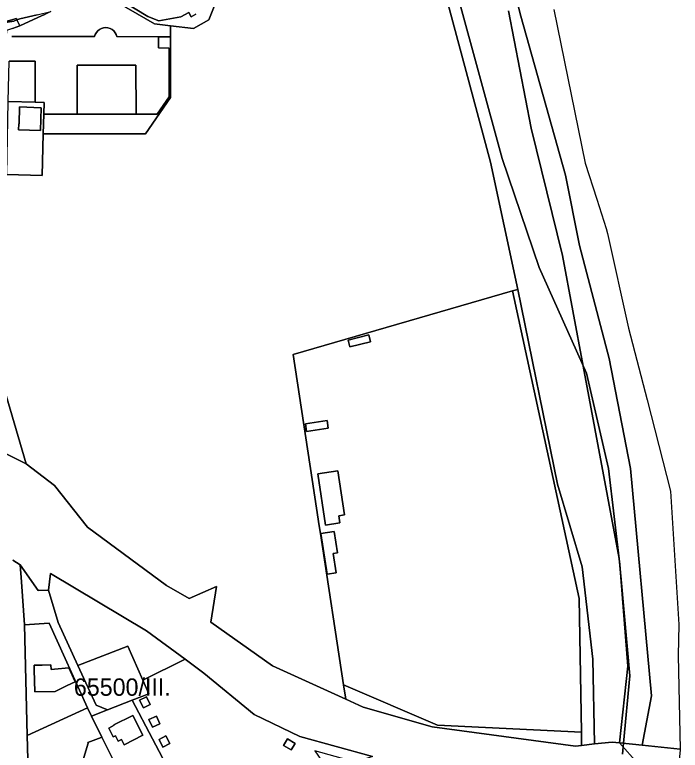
# Model space of a CAD drawing. Extents: x -502026 to -497664, y -1143484 to -1138019.
# Drawn here: x -497970.3 to -497663.8, y -1140661.2 to -1140322.7 of the extents above; entities that cross this region are included whole.
import ezdxf

# ---------------------------------------------------------------- set-up
doc = ezdxf.new("R2010")
doc.units = 0
for name, color, linetype in [('25', 7, 'Continuous'), ('49', 7, 'Continuous'), ('55', 7, 'Continuous'), ('62', 7, 'Continuous'), ('7', 7, 'Continuous')]:
    doc.layers.add(name, color=color, linetype=linetype)

msp = doc.modelspace()

# ---------------------------------------------------------------- linework, layer by layer
at = {"layer": '25'}
for points in [[(-497936.82, -1140641.63), (-497964.62, -1140654.4), (-497965.83, -1140603.55), (-497954.43, -1140602.68)], [(-497805.55, -1140664.16), (-497813.42, -1140666.63), (-497832.11, -1140661.41), (-497812.62, -1140689.68), (-497805.57, -1140699.94), (-497798.59, -1140710.5), (-497772.17, -1140748.77), (-497794.67, -1140765.2), (-497816.79, -1140777.36), (-497824.82, -1140780.89), (-497825.15, -1140780.18), (-497841.74, -1140744.45), (-497858.43, -1140708.44), (-497861.67, -1140701.6), (-497877.43, -1140665.94), (-497897.52, -1140673.81), (-497916.16, -1140638.1), (-497908.61, -1140635.26), (-497911.38, -1140628.95), (-497891.85, -1140619.36), (-497883.28, -1140625.68), (-497860.05, -1140644.73), (-497839.03, -1140654.82)], [(-497953.61, -1140621.9), (-497957.75, -1140621.99), (-497961.43, -1140622.09), (-497961.3, -1140624.22), (-497961.03, -1140634.35), (-497951.67, -1140634.13), (-497946.11, -1140631.47), (-497942.55, -1140629.76), (-497945.46, -1140623.23), (-497951.94, -1140623.97), (-497953.55, -1140624.01)], [(-497907.9, -1140640.14), (-497909.7, -1140636.6), (-497912.83, -1140638.13), (-497911.04, -1140641.71)], [(-497897.52, -1140673.81), (-497917.07, -1140681.47), (-497919.36, -1140677), (-497930.13, -1140655.18), (-497934.91, -1140645.49), (-497927.56, -1140642.59), (-497916.16, -1140638.1)], [(-497934.91, -1140645.49), (-497930.13, -1140655.18), (-497930.45, -1140655.3), (-497936.6, -1140657.61), (-497936.45, -1140658.02), (-497940.31, -1140670.66), (-497939.64, -1140672.96), (-497941.84, -1140673.79), (-497940.2, -1140678.14), (-497938, -1140677.31), (-497937.04, -1140679.84), (-497935.87, -1140682.92), (-497941.97, -1140685.1), (-497953.46, -1140689.2), (-497963.48, -1140692.74), (-497964.62, -1140654.4), (-497936.82, -1140641.63)], [(-497911.25, -1140654.34), (-497915.95, -1140645.14), (-497924.61, -1140649.56), (-497924.51, -1140649.74), (-497927.05, -1140651.04), (-497925.01, -1140655.03), (-497923.97, -1140654.5), (-497922.7, -1140656.99), (-497921.2, -1140656.22), (-497919.95, -1140658.67)], [(-497903.46, -1140649.05), (-497905.1, -1140645.45), (-497908.54, -1140646.99), (-497906.81, -1140650.6)], [(-497898.92, -1140658.15), (-497900.7, -1140654.59), (-497903.83, -1140656.2), (-497902.05, -1140659.73)], [(-497841.21, -1140658.03), (-497844.68, -1140655.93), (-497846.51, -1140658.98), (-497843.04, -1140661.04)]]:
    msp.add_lwpolyline(points, close=True, dxfattribs=at)
at = {"layer": '49'}
msp.add_lwpolyline([(-497722.04, -1140320.29), (-497707.7, -1140391.05), (-497702.32, -1140407.61), (-497697.93, -1140421.1), (-497697.4, -1140423.44), (-497687.61, -1140466.9), (-497679.11, -1140500), (-497668.31, -1140542.04), (-497664.47, -1140603.39), (-497664.79, -1140617.64), (-497663.84, -1140660.72), (-497681.38, -1140658.88), (-497677.05, -1140636.15), (-497686.75, -1140531.6), (-497696.64, -1140480.95), (-497710.3, -1140428.93), (-497716.71, -1140396.51), (-497737.24, -1140323.39), (-497754.99, -1140253.14)], dxfattribs=at)
msp.add_lwpolyline([(-497681.38, -1140658.88), (-497663.84, -1140660.72), (-497663.83, -1140661.21), (-497664.59, -1140668.32), (-497664.63, -1140668.75), (-497665.07, -1140672.88), (-497665.12, -1140673.27), (-497666.55, -1140686.68), (-497686.23, -1140684.57), (-497699.12, -1140683.04), (-497683.84, -1140672.19), (-497683.37, -1140667.28), (-497691.84, -1140657.78)], close=True, dxfattribs=at)
at = {"layer": '55'}
for points in [[(-497691.84, -1140657.78), (-497695.17, -1140657.43), (-497703.28, -1140658.33), (-497704.11, -1140619.29), (-497708.97, -1140576.79), (-497720.33, -1140538.79), (-497738.59, -1140449.11), (-497751.17, -1140390.61), (-497791.01, -1140242.45), (-497784.27, -1140241.09), (-497766.22, -1140314.06), (-497745.87, -1140388.9), (-497728.83, -1140438.98), (-497707.05, -1140487.75), (-497696.93, -1140531.58), (-497691.64, -1140575.72), (-497688.04, -1140622.46)], [(-497956.48, -1140322.59), (-497957.69, -1140323.15), (-497967.99, -1140327.91), (-497969.28, -1140325.11), (-497967.92, -1140324.62), (-497960.03, -1140322.72), (-497953.65, -1140321.27)], [(-497967.99, -1140327.91), (-497971.3, -1140329.05), (-497974.13, -1140330.03), (-497979.11, -1140332.27), (-497981.94, -1140332.89), (-497988.1, -1140334.24), (-497997.64, -1140334.52), (-498008.74, -1140334.09), (-498008.64, -1140332.24), (-498003.4, -1140332.22), (-497996.47, -1140330.02), (-497994.85, -1140329.91), (-497988.93, -1140329.3), (-497983.89, -1140328.52), (-497977.71, -1140326.79), (-497970.78, -1140325.66), (-497969.28, -1140325.11)], [(-497969.28, -1140325.11), (-497970.78, -1140325.66), (-497977.71, -1140326.79), (-497969.56, -1140324.51)], [(-497974.21, -1140332.78), (-497974.36, -1140337.77), (-497974.54, -1140344.08), (-497978.1, -1140485.38), (-497965, -1140529.36), (-497976.1, -1140523.81), (-497986.26, -1140484.05), (-497986.07, -1140460.79), (-497984.83, -1140425.08), (-497983.81, -1140385.99), (-497982.32, -1140365.37), (-497981.91, -1140339.55), (-497981.94, -1140332.89), (-497979.11, -1140332.27), (-497974.13, -1140330.03)], [(-497914.35, -1140368.48), (-497941.57, -1140368.44), (-497941.52, -1140345.9), (-497914.49, -1140345.89)], [(-497958.18, -1140365.56), (-497958.37, -1140375.97), (-497968.51, -1140375.66), (-497968.45, -1140372.95), (-497968.28, -1140372.94), (-497968.08, -1140365.19)], [(-497709.37, -1140652.85), (-497775.61, -1140649.69), (-497818.9, -1140631.1), (-497829.51, -1140561.5), (-497830.05, -1140557.94), (-497833.28, -1140536.67), (-497842.03, -1140479.04), (-497741.17, -1140449.86), (-497710.44, -1140591.41)], [(-497703.28, -1140658.33), (-497709.26, -1140658.99), (-497709.37, -1140652.85), (-497710.44, -1140591.41), (-497741.17, -1140449.86), (-497738.59, -1140449.11), (-497720.33, -1140538.79), (-497708.97, -1140576.79), (-497704.11, -1140619.29)], [(-497806.46, -1140473.22), (-497815.94, -1140475.6), (-497816.71, -1140472.44), (-497807.24, -1140470.07)], [(-497806.46, -1140473.22), (-497807.24, -1140470.07), (-497816.71, -1140472.44), (-497815.94, -1140475.6)], [(-497825.97, -1140513.05), (-497826.5, -1140509.53), (-497836.46, -1140511.03), (-497835.93, -1140514.57)], [(-497825.97, -1140513.05), (-497835.93, -1140514.57), (-497836.46, -1140511.03), (-497826.5, -1140509.53)], [(-497820.64, -1140556.62), (-497821.12, -1140553.31), (-497818.38, -1140552.91), (-497821.47, -1140532.63), (-497830.76, -1140534.04), (-497827.17, -1140557.61)], [(-497820.64, -1140556.62), (-497827.17, -1140557.61), (-497830.76, -1140534.04), (-497821.47, -1140532.63), (-497818.38, -1140552.91), (-497821.12, -1140553.31)], [(-497822.35, -1140579.51), (-497826.41, -1140580.14), (-497829.32, -1140561.49), (-497823.19, -1140560.53), (-497821.65, -1140570.31), (-497823.72, -1140570.64)], [(-497822.35, -1140579.51), (-497823.72, -1140570.64), (-497821.65, -1140570.31), (-497823.19, -1140560.53), (-497829.32, -1140561.49), (-497826.41, -1140580.14)], [(-497954.83, -1140587.61), (-497950.37, -1140602.37), (-497941.23, -1140622.22), (-497932.86, -1140640.39), (-497927.56, -1140642.59), (-497934.91, -1140645.49), (-497936.82, -1140641.63), (-497954.43, -1140602.68), (-497965.83, -1140603.55), (-497967.22, -1140583.76), (-497967.87, -1140575.85), (-497959.56, -1140587.67)], [(-497953.61, -1140621.9), (-497953.55, -1140624.01), (-497951.94, -1140623.97), (-497945.46, -1140623.23), (-497942.55, -1140629.76), (-497946.11, -1140631.47), (-497951.67, -1140634.13), (-497961.03, -1140634.35), (-497961.3, -1140624.22), (-497961.43, -1140622.09), (-497957.75, -1140621.99)], [(-497709.37, -1140652.85), (-497709.26, -1140658.99), (-497712.1, -1140659.31), (-497778.08, -1140650.46), (-497809.84, -1140641.44), (-497817.9, -1140637.68), (-497818.9, -1140631.1), (-497775.61, -1140649.69)], [(-497907.9, -1140640.14), (-497911.04, -1140641.71), (-497912.83, -1140638.13), (-497909.7, -1140636.6)], [(-497911.25, -1140654.34), (-497919.95, -1140658.67), (-497921.2, -1140656.22), (-497922.7, -1140656.99), (-497923.97, -1140654.5), (-497925.01, -1140655.03), (-497927.05, -1140651.04), (-497924.51, -1140649.74), (-497924.61, -1140649.56), (-497915.95, -1140645.14)], [(-497903.46, -1140649.05), (-497906.81, -1140650.6), (-497908.54, -1140646.99), (-497905.1, -1140645.45)], [(-497919.36, -1140677), (-497934.71, -1140682.5), (-497935.87, -1140682.92), (-497937.04, -1140679.84), (-497938, -1140677.31), (-497940.2, -1140678.14), (-497941.84, -1140673.79), (-497939.64, -1140672.96), (-497940.31, -1140670.66), (-497936.45, -1140658.02), (-497936.6, -1140657.61), (-497930.45, -1140655.3), (-497930.13, -1140655.18)], [(-497898.92, -1140658.15), (-497902.05, -1140659.73), (-497903.83, -1140656.2), (-497900.7, -1140654.59)], [(-497841.21, -1140658.03), (-497843.04, -1140661.04), (-497846.51, -1140658.98), (-497844.68, -1140655.93)]]:
    msp.add_lwpolyline(points, close=True, dxfattribs=at)
for points in [[(-497754.99, -1140253.14), (-497737.24, -1140323.39), (-497716.71, -1140396.51), (-497710.3, -1140428.93), (-497696.64, -1140480.95), (-497686.75, -1140531.6), (-497677.05, -1140636.15), (-497681.38, -1140658.88), (-497691.84, -1140657.78), (-497688.04, -1140622.46), (-497691.64, -1140575.72), (-497696.93, -1140531.58), (-497707.05, -1140487.75), (-497728.83, -1140438.98), (-497745.87, -1140388.9), (-497766.22, -1140314.06)], [(-497886.97, -1140322.51), (-497889.09, -1140323.65), (-497890.11, -1140321.77), (-497893.76, -1140323.74), (-497904.02, -1140325.5), (-497909.07, -1140323.48), (-497921.46, -1140316.07)], [(-497960.03, -1140322.72), (-497967.92, -1140324.62), (-497969.28, -1140325.11), (-497969.56, -1140324.51), (-497977.71, -1140326.79)], [(-497971.59, -1140332.78), (-497933.54, -1140332.75), (-497933.21, -1140331.77), (-497932.72, -1140330.89), (-497932.04, -1140330.12), (-497931.26, -1140329.48), (-497930.35, -1140329.02), (-497929.37, -1140328.73), (-497928.37, -1140328.64), (-497927.36, -1140328.72), (-497926.38, -1140329.03), (-497925.5, -1140329.54), (-497924.72, -1140330.21), (-497924.09, -1140331.03), (-497923.66, -1140331.85), (-497923.35, -1140332.77), (-497904.17, -1140332.91), (-497904.12, -1140338.01), (-497899.18, -1140338.11), (-497899.14, -1140360.49), (-497904.65, -1140368.49), (-497914.35, -1140368.48), (-497914.49, -1140345.89), (-497941.52, -1140345.9), (-497941.57, -1140368.44), (-497956.96, -1140368.5), (-497956.81, -1140363.09), (-497960.97, -1140362.97), (-497960.94, -1140344.13), (-497972.87, -1140344.1)], [(-497976.1, -1140523.81), (-497965, -1140529.36), (-497952.03, -1140539.4), (-497936.83, -1140558.56), (-497900.36, -1140585.38), (-497889.91, -1140591.32), (-497877.4, -1140585.86), (-497879.94, -1140602.25), (-497851.6, -1140622.37), (-497817.9, -1140637.68), (-497809.84, -1140641.44), (-497778.08, -1140650.46), (-497712.1, -1140659.31), (-497709.26, -1140658.99), (-497703.28, -1140658.33), (-497695.17, -1140657.43), (-497691.84, -1140657.78), (-497683.37, -1140667.28)], [(-497971.23, -1140573.7), (-497967.87, -1140575.85), (-497967.22, -1140583.76), (-497965.83, -1140603.55), (-497964.62, -1140654.4), (-497963.48, -1140692.74), (-497963.31, -1140698.84), (-497963.1, -1140704.84), (-497962.01, -1140740.8), (-497961.95, -1140749.45), (-497966.8, -1140776.46), (-497970.28, -1140795.81), (-497979.66, -1140835.43)], [(-497805.55, -1140664.16), (-497839.03, -1140654.82), (-497860.05, -1140644.73), (-497883.28, -1140625.68), (-497891.85, -1140619.36), (-497909.67, -1140606.22), (-497953.88, -1140579.91), (-497954.83, -1140587.61), (-497959.56, -1140587.67), (-497967.87, -1140575.85), (-497971.23, -1140573.7)]]:
    msp.add_lwpolyline(points, dxfattribs=at)
at = {"layer": '62'}
for points in [[(-497743, -1140321), (-497732.5, -1140375), (-497718, -1140433.5), (-497708.49, -1140484.53), (-497692, -1140573), (-497691.1, -1140582.66), (-497687, -1140627), (-497690.01, -1140657.97), (-497690.17, -1140659.65), (-497690.5, -1140663)], [(-497690.5, -1140663), (-497690.17, -1140659.65), (-497690.01, -1140657.97), (-497687, -1140627), (-497691.1, -1140582.66), (-497692, -1140573), (-497708.49, -1140484.53), (-497718, -1140433.5), (-497732.5, -1140375), (-497743, -1140321)], [(-497722.04, -1140320.29), (-497707.7, -1140391.05), (-497702.32, -1140407.61), (-497697.93, -1140421.1), (-497697.4, -1140423.44), (-497687.61, -1140466.9), (-497679.11, -1140500), (-497668.31, -1140542.04), (-497664.47, -1140603.39), (-497664.79, -1140617.64), (-497663.84, -1140660.72), (-497663.83, -1140661.21), (-497664.59, -1140668.32)]]:
    msp.add_lwpolyline(points, dxfattribs=at)
at = {"layer": '7'}
for points in [[(-497791.01, -1140242.45), (-497751.17, -1140390.61), (-497738.59, -1140449.11), (-497741.17, -1140449.86), (-497842.03, -1140479.04), (-497833.28, -1140536.67), (-497830.05, -1140557.94), (-497829.51, -1140561.5), (-497818.9, -1140631.1), (-497817.9, -1140637.68), (-497851.6, -1140622.37), (-497879.94, -1140602.25), (-497877.4, -1140585.86), (-497889.91, -1140591.32), (-497900.36, -1140585.38), (-497936.83, -1140558.56), (-497952.03, -1140539.4), (-497965, -1140529.36), (-497978.1, -1140485.38)], [(-497973.98, -1140396.25), (-497957.73, -1140396.69), (-497957.21, -1140377.58), (-497910.06, -1140377.52), (-497898.6, -1140360.76), (-497898.53, -1140332.95), (-497898.51, -1140327.82), (-497888.02, -1140329.02), (-497880.89, -1140325.03), (-497874.77, -1140309.65)], [(-497874.77, -1140309.65), (-497880.89, -1140325.03), (-497888.02, -1140329.02), (-497898.51, -1140327.82), (-497905.91, -1140326.96), (-497926.91, -1140314.69)], [(-497926.91, -1140314.69), (-497905.91, -1140326.96), (-497898.51, -1140327.82), (-497898.53, -1140332.95), (-497904.17, -1140332.91), (-497923.35, -1140332.77), (-497923.66, -1140331.85), (-497924.09, -1140331.03), (-497924.72, -1140330.21), (-497925.5, -1140329.54), (-497926.38, -1140329.03), (-497927.36, -1140328.72), (-497928.37, -1140328.64), (-497929.37, -1140328.73), (-497930.35, -1140329.02), (-497931.26, -1140329.48), (-497932.04, -1140330.12), (-497932.72, -1140330.89), (-497933.21, -1140331.77), (-497933.54, -1140332.75), (-497971.59, -1140332.78)], [(-497921.46, -1140316.07), (-497909.07, -1140323.48), (-497904.02, -1140325.5), (-497893.76, -1140323.74), (-497890.11, -1140321.77), (-497889.09, -1140323.65), (-497886.97, -1140322.51)], [(-497971.3, -1140329.05), (-497967.99, -1140327.91), (-497957.69, -1140323.15), (-497956.48, -1140322.59)]]:
    msp.add_lwpolyline(points, dxfattribs=at)
for points in [[(-497898.53, -1140332.95), (-497898.6, -1140360.76), (-497910.06, -1140377.52), (-497957.21, -1140377.58), (-497956.96, -1140368.5), (-497941.57, -1140368.44), (-497914.35, -1140368.48), (-497904.65, -1140368.49), (-497899.14, -1140360.49), (-497899.18, -1140338.11), (-497904.12, -1140338.01), (-497904.17, -1140332.91)], [(-497960.97, -1140362.97), (-497973.26, -1140362.64), (-497972.87, -1140344.1), (-497960.94, -1140344.13)], [(-497960.97, -1140362.97), (-497956.81, -1140363.09), (-497956.96, -1140368.5), (-497957.21, -1140377.58), (-497957.73, -1140396.69), (-497973.98, -1140396.25), (-497973.26, -1140362.64)], [(-497958.18, -1140365.56), (-497968.08, -1140365.19), (-497968.28, -1140372.94), (-497968.45, -1140372.95), (-497968.51, -1140375.66), (-497958.37, -1140375.97)], [(-497891.85, -1140619.36), (-497911.38, -1140628.95), (-497918.25, -1140613.28), (-497941.23, -1140622.22), (-497950.37, -1140602.37), (-497954.83, -1140587.61), (-497953.88, -1140579.91), (-497909.67, -1140606.22)], [(-497911.38, -1140628.95), (-497908.61, -1140635.26), (-497916.16, -1140638.1), (-497927.56, -1140642.59), (-497932.86, -1140640.39), (-497941.23, -1140622.22), (-497918.25, -1140613.28)]]:
    msp.add_lwpolyline(points, close=True, dxfattribs=at)

# ---------------------------------------------------------------- texts
at = {"layer": '62'}
msp.add_text('65500/III.', height=8, dxfattribs=at).set_placement((-497943.07, -1140636.15))

doc.saveas('drawing.dxf')
